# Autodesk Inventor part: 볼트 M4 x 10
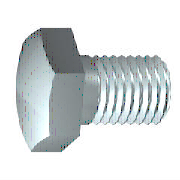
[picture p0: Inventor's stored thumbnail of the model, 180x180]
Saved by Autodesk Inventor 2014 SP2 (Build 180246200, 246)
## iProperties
Created: 2012-02
Part Number: 볼트 M4 x 10
Material: 스테인리스강
Description: 6각 머리 나사
Document SubType Name: Modeling
Standard: ISO 4017
Designer: mduedu
Standard Revision: Third edition 1999-08-15
Standards Organization: ISO
Language: ko-KR
Size Designation: M4 x 10
Categories: <MemberInstance><Categories><Category DisplayName="조임쇠" InternalName="e4da775c-781d-43d5-af7c-5136215cf5a6" Mnemonic="FSTN"><Category DisplayName="볼트" InternalN
Density: 8.08 g/cm^3
Appearance: 기본값
IsCustomPart: 0
Author: mduedu
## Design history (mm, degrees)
sketch "스케치1"
  geometry: L1 (0, 3.015)-(0, 2); L2 (2.1, 2)-(10, 2); L3 (10, 2)-(10, 0); L4 (10, 0)-(-0.4, 0); L5 (-2.48, 0)-(12.08, 0) reference; L6 (-0.4, 0)-(-0.4, 3.015); L7 (-0.4, 3.015)-(0, 3.015); L8 (2.1, 2)-(1.67, 2); L9 (1.67, 2)-(0, 2); L10 (0, -0.603)-(0, 3.618) reference
  constraints: 16 end point, 2 collinear, 2 perpendicular, 1 parallel
  dimensions: "d0" = 10 distance between parallel lines of L3 L1 (= NLG); "d1" = 7.9 distance from line of L2.start L3 (= GEL); "d2" = 4 diameter of L2 L4 (= GD); "d9" = 0.4001 distance between parallel lines of L6 L1 (computed from SD); "d10" = 6.03 diameter of L7 L4 (= SD2); "d13" = 0.42952 distance of L2.start L8.end (computed from GAL); "d14" = 4 diameter of L9 L4 (= BDM)
revolve "본체" sketch "스케치1" stored, may be unused: angle "d12" = 90 deg
sketch "스케치2"
  geometry: L1 (0, 4.041)-(3.5, 2.021); L2 (3.5, 2.021)-(3.5, -2.021); L3 (3.5, -2.021)-(0, -4.041); L4 (0, -4.041)-(-3.5, -2.021); L5 (-3.5, -2.021)-(-3.5, 2.021); L6 (-3.5, 2.021)-(0, 4.041); 2 further points
  constraints: 12 end point, 1 coincident, 1 vertical, 11 other
  dimensions: "d11" = 7 distance between parallel lines of L5 L2 (= SW)
extrude "머리" join sketch "스케치2" distance "d3" = 2.4 (= KOH - SD); taper "d4" = 0 deg
sketch "스케치4"
  geometry: L1 (-2.8, 3.5)-(-2.8, 4.041); L2 (-2.8, 4.041)-(-2.487, 4.041); L3 (-2.487, 4.041)-(-2.8, 3.5); L4 (-3.28, 0)-(0.08, 0) reference; L5 (-0.4, 4.041)-(-2.8, 4.041) reference; L6 (-2.8, 2.021)-(-2.8, 4.041) reference
  constraints: 6 end point, 2 collinear, 1 perpendicular, 1 vertical
  dimensions: "d5" = 30 deg angle of L3 L1 (= ANG1); "d19" = 7 diameter of L1.start L4 (= SW0)
revolve "모따기1" sketch "스케치4" stored, may be unused: angle "d21" = 90 deg
workplane "Work Plane1"
body "Solid1"
feature "스레드" dims "d15" = 7.9 (= GEL), "d16" = 0
chamfer "모따기2" distance "d6" = 0.42941 (= -0.5 x SPD + 0.5 x GD); stored, may be unused: second distance "d7" = 0.42952 (computed from GUL), angle "d55" = 45 deg
other parameters: "NLG" = 10 [user parameter; used in 1 equation term], "GD" = 4 (= NND) [user parameter; used in 2 equation terms], "BDM" = 4 (= NND) [user parameter; used in 1 equation term], "KOH" = 2.8 [user parameter; used in 1 equation term], "GEL" = 7.9 [user parameter; used in 2 equation terms], "SW" = 7 [user parameter; used in 2 equation terms], "SW0" = 7 (= SW) [user parameter; used in 1 equation term], "SPD" = 3.14117 (= NND - 1.2269 x PTC) [user parameter; used in 1 equation term], "SD2" = 6.03 [user parameter; used in 2 equation terms], "SD" = 0.4 [user parameter; used in 2 equation terms], "ANG1" = 30 deg [user parameter; used in 1 equation term], "GAL" = 0.42941 (= 0.61345 x PTC) [user parameter; used in 1 equation term], "GUL" = 0.42941 (= 0.61345 x PTC) [user parameter; used in 1 equation term], "d8" = 0, "RR" = 0.2 [user parameter], "d57" = 0, "d58" = 0, "TPU" = 14.28571 (computed from PTC) [user parameter], "GD1" = 3.14117 (= THREADDIA - 1.2269 x PTC) [user parameter], "THREADDIA" = 4 [user parameter; used in 1 equation term], "SDH" = 6.03 (= SD2) [user parameter], "SDHG" = 2.1 [user parameter], "TOA" = 30 deg [user parameter], "PTC" = 0.7 [user parameter; used in 5 equation terms], "NND" = 4 [user parameter; used in 3 equation terms], "E0" = 8.085 [user parameter]
